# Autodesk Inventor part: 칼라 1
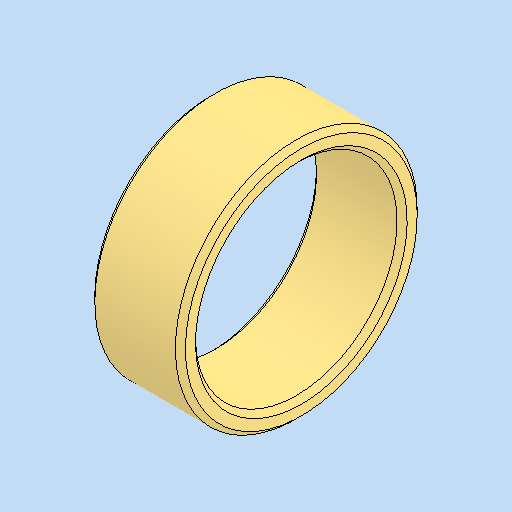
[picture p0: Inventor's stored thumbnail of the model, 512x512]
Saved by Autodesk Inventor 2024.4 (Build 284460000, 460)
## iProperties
Created: 2025-11
Part Number: 칼라 1
Material: 강철, 연강
Document SubType Name: Modeling
Designer: home
Density: 7.85 g/cm^3
Appearance: 기본값
Author: jhkim
Sending System: Autodesk Inventor 2026
Preprocessor: ST-DEVELOPER v20.1
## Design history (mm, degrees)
feature "솔리드1"
node "솔리드2"
